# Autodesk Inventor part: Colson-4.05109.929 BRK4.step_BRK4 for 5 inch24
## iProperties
Created: 2010-10
Part Number: Colson-4.05109.929 BRK4.step_BRK4 for 5 inch24
Document SubType Name: Modeling
Designer: Administrator
Density: 7.85 g/cm^3
Material: Steel
Mass: 22.22 g
Surface Area: 20.8622 cm^2
Volume: 2.83058 cm^3
Author: Administrator
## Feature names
1. Base1
